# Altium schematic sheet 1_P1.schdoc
size 429 x 307 mm; Symbol: Drawing-Symbol_A4; Device: Drawing-Symbol_A4; Company: 嘉立创EDA; Version: V1.0; Page Size: A4; @Project Name: 数控直流电源v3; @Page Count: 1; @Update Date: 2025-11-23; @Create Date: 2025-11-23; @Schematic Name: v3; @Page No: 1; @Page Name: P1; @Create Time: 16:35:47; @Update Time: 18:46:06; Width: 1655; Height: 1170; Region Start: 1; X Region Count: 6; Y Region Count: 4; Blade Width: 10; Title Block Position: 3; @Board Name: Board1
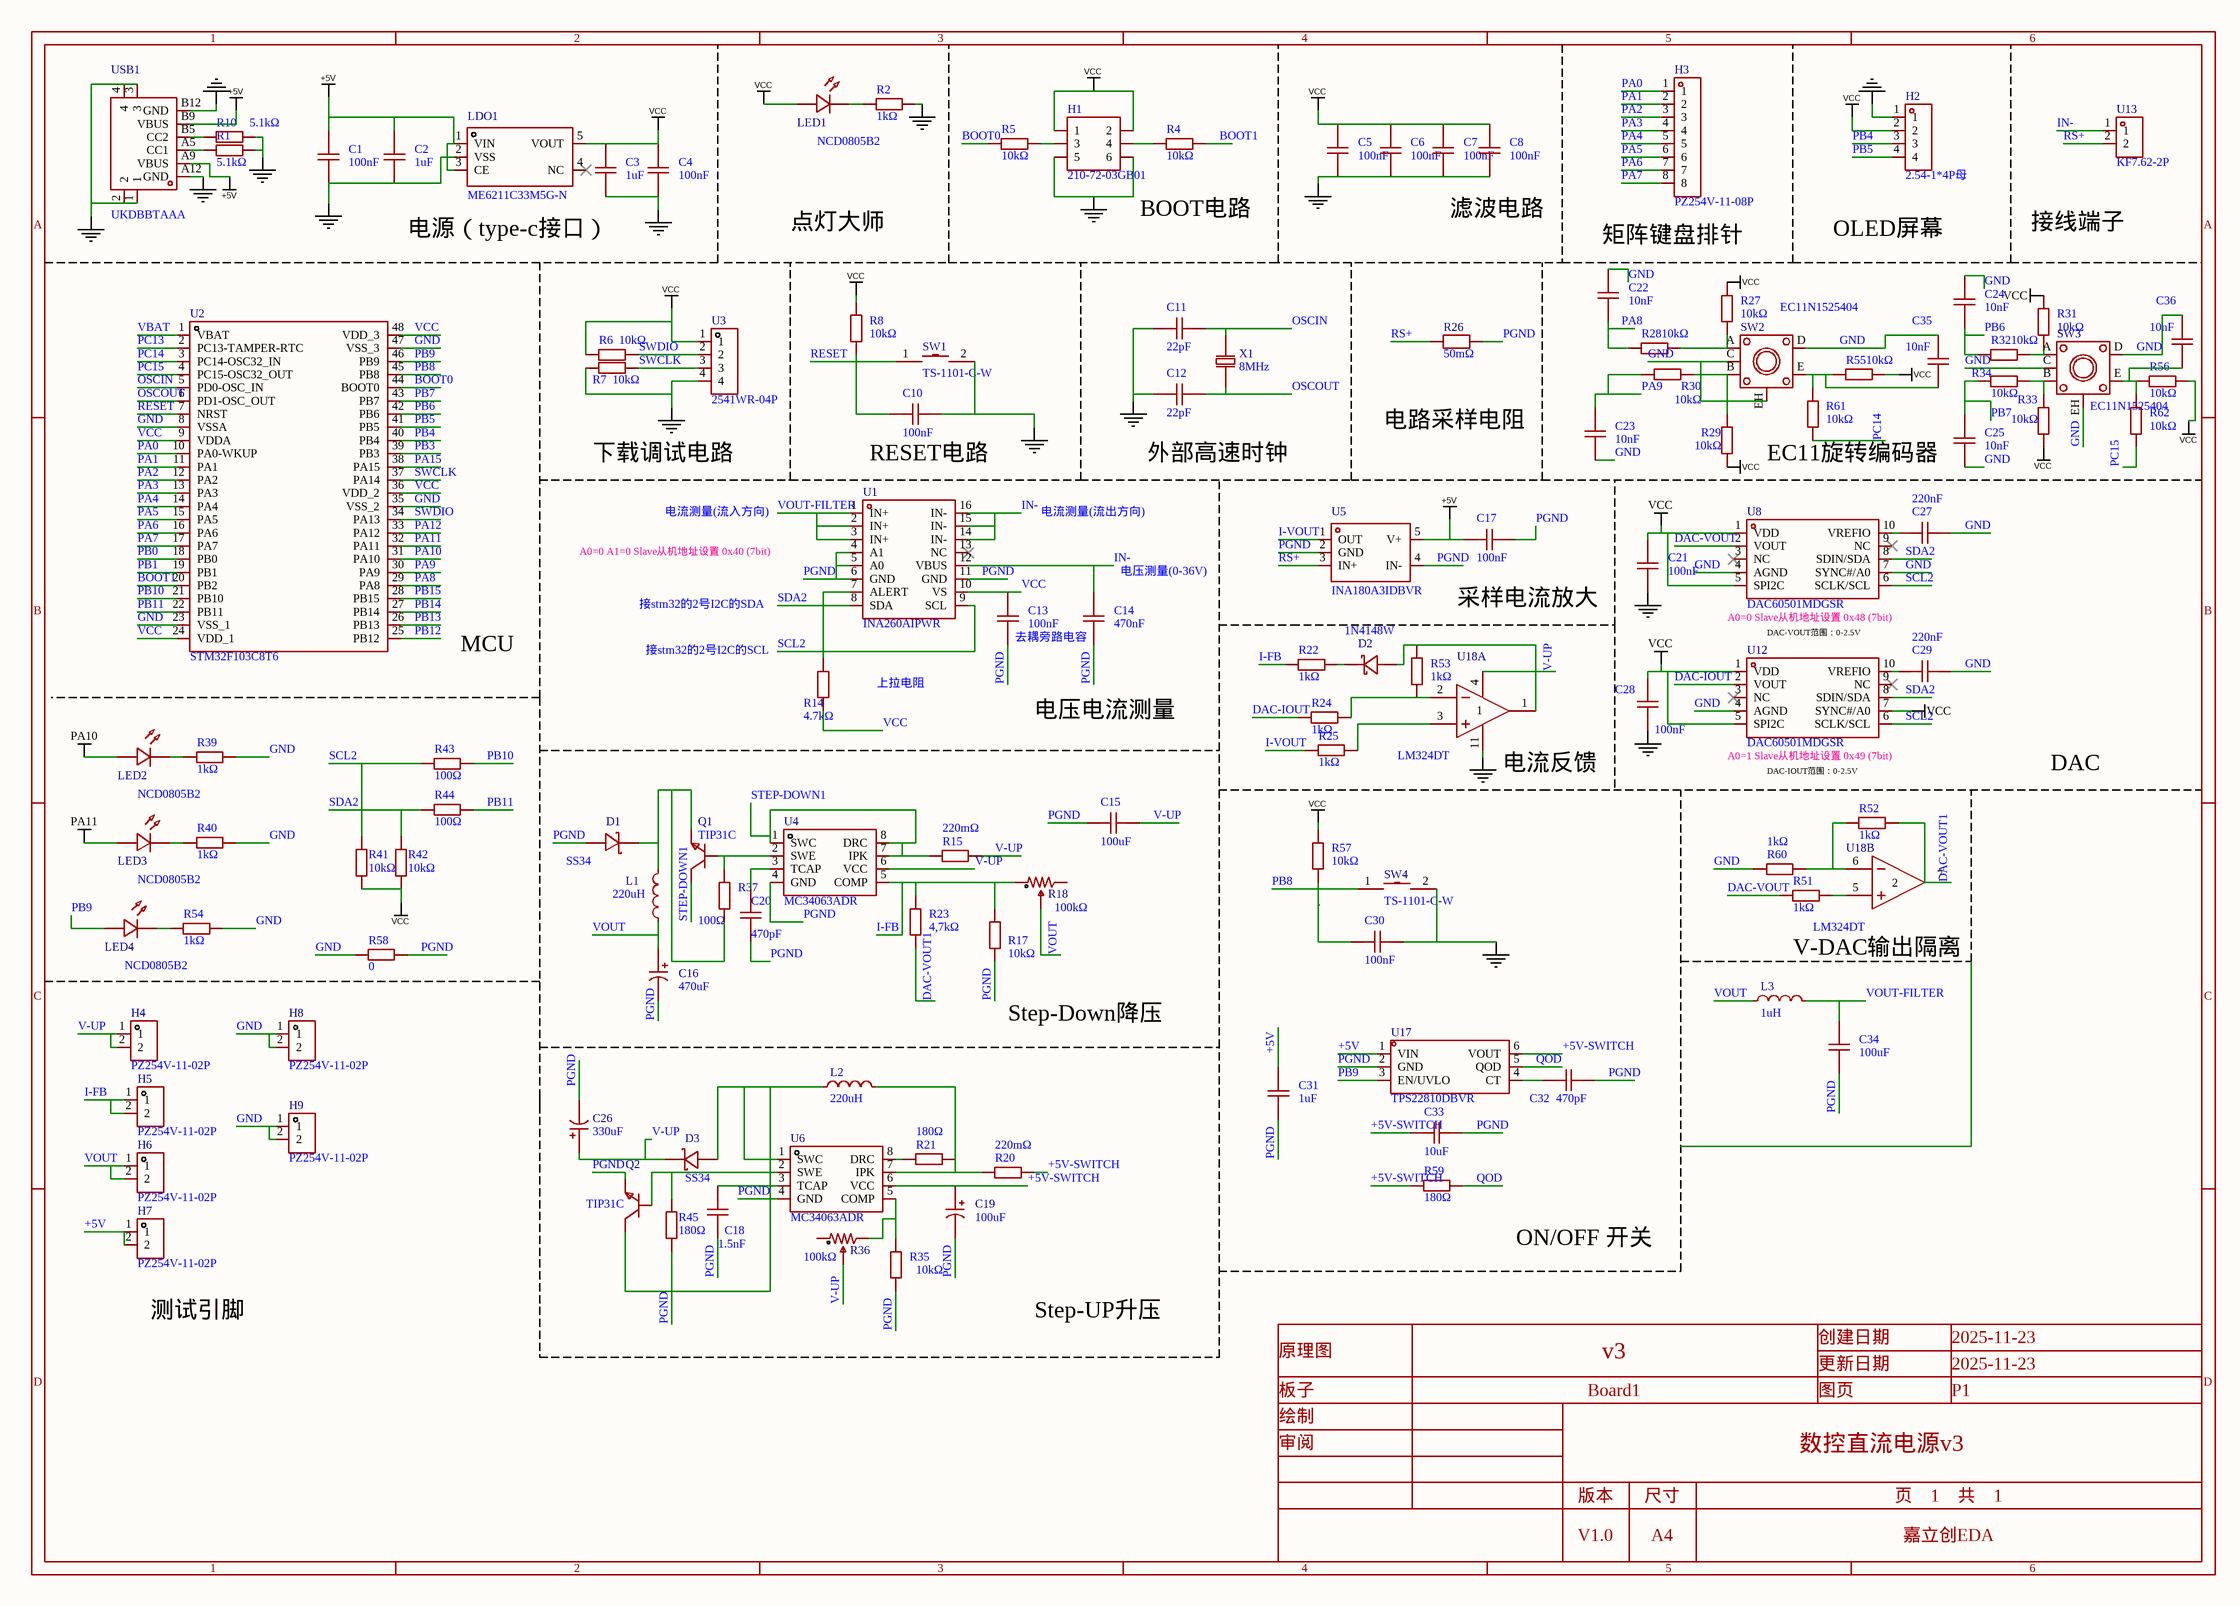
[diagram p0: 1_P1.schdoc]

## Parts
C1  100nF  [C0805]
C2  1uF  [C0805]
C3  1uF  [C0805]
C4  100nF  [C0805]
C5  100nF  [C0805]
C6  100nF  [C0805]
C7  100nF  [C0805]
C8  100nF  [C0805]
C10  100nF  [C0805]
C11  22pF  [C0805]
C12  22pF  [C0805]
C13  100nF  [C0805]
C14  470nF  [C0805]
C15  100uF  [CAP-SMD_BD6.3-L6.6-W6.6-RD]
C16  470uF  [CAP-SMD_BD8.0-L8.3-W8.3-LS9.0-FD_H10.5]
C17  100nF  [C0805]
C18  1.5nF  [C0805]
C19  100uF  [CAP-SMD_BD6.3-L6.6-W6.6-RD]
C20  470pF  [C0805]
C21  100nF  [C0805]
C22  10nF  [C0805]
C23  10nF  [C0805]
C24  10nF  [C0805]
C25  10nF  [C0805]
C26  330uF  [CAP-SMD_BD10.0-L10.3-W10.3-FD-LS11.0_H12.0]
C27  220nF  [C0805]
C28  100nF  [C0805]
C29  220nF  [C0805]
C30  100nF  [C0805]
C31  1uF  [C0805]
C32  470pF  [C0805]
C33  10uF  [C0805]
C34  100uF  [CAP-SMD_BD6.3-L6.6-W6.6-RD]
C35  10nF  [C0805]
C36  10nF  [C0805]
D1  SS34  [SMA_L4.3-W2.6-LS5.0-FD]
D2  1N4148W  [SOD-123_L2.7-W1.6-LS3.7-FD]
D3  SS34  [SMA_L4.3-W2.6-LS5.0-FD]
H1  210-72-03GB01  [HDR-TH_6P-P2.54-V-R2-C3-S2.54_A2541WV-2X3P]
H2  2.54-1*4P母  [HDR-TH_4P-P2.54-V-F]
H3  PZ254V-11-08P  [HDR-TH_8P-P2.54-V-M]
H4  PZ254V-11-02P  [HDR-TH_2P-P2.54-V-M]
H5  PZ254V-11-02P  [HDR-TH_2P-P2.54-V-M]
H6  PZ254V-11-02P  [HDR-TH_2P-P2.54-V-M]
H7  PZ254V-11-02P  [HDR-TH_2P-P2.54-V-M]
H8  PZ254V-11-02P  [HDR-TH_2P-P2.54-V-M]
H9  PZ254V-11-02P  [HDR-TH_2P-P2.54-V-M]
L1  220uH  [IND-SMD_L12.3-W12.3_SMDRI127]
L2  220uH  [IND-SMD_L12.3-W12.3_SMDRI127]
L3  1uH  [IND-SMD_L7.0-W6.6]
LDO1  ME6211C33M5G-N  [SOT-23-5_L3.0-W1.7-P0.95-LS2.8-BL]
LED1  NCD0805B2  [LED0805-R-RD]
LED2  NCD0805B2  [LED0805-R-RD]
LED3  NCD0805B2  [LED0805-R-RD]
LED4  NCD0805B2  [LED0805-R-RD]
Q1  TIP31C  [TO-220-3_L10.0-W4.5-P2.54-L]
Q2  TIP31C  [TO-220-3_L10.0-W4.5-P2.54-L]
R1  5.1kΩ  [R0805]
R2  1kΩ  [R0805]
R4  10kΩ  [R0805]
R5  10kΩ  [R0805]
R6  10kΩ  [R0805]
R7  10kΩ  [R0805]
R8  10kΩ  [R0805]
R10  5.1kΩ  [R0805]
R14  4.7kΩ  [R0805]
R15  220mΩ  [R1206]
R17  10kΩ  [R0805]
R18  100kΩ  [RES-ADJ-TH_3296W]
R20  220mΩ  [R1206]
R21  180Ω  [R0805]
R22  1kΩ  [R0805]
R23  4,7kΩ  [R0805]
R24  1kΩ  [R0805]
R25  1kΩ  [R0805]
R26  50mΩ  [R1206]
R27  10kΩ  [R0805]
R28  10kΩ  [R0805]
R29  10kΩ  [R0805]
R30  10kΩ  [R0805]
R31  10kΩ  [R0805]
R32  10kΩ  [R0805]
R33  10kΩ  [R0805]
R34  10kΩ  [R0805]
R35  10kΩ  [R0805]
R36  100kΩ  [RES-ADJ-TH_3296W-1-203]
R37  100Ω  [R0805]
R39  1kΩ  [R0805]
R40  1kΩ  [R0805]
R41  10kΩ  [R0805]
R42  10kΩ  [R0805]
R43  100Ω  [R0805]
R44  100Ω  [R0805]
R45  180Ω  [R0805]
R51  1kΩ  [R0805]
R52  1kΩ  [R0805]
R53  1kΩ  [R0805]
R54  1kΩ  [R0805]
R55  10kΩ  [R0805]
R56  10kΩ  [R0805]
R57  10kΩ  [R0805]
R58  0  [R0805]
R59  180Ω  [R0805]
R60  1kΩ  [R0805]
R61  10kΩ  [R0805]
R62  10kΩ  [R0805]
SW1  TS-1101-C-W  [SW-SMD_L6.0-W3.3-LS8.0]
SW2  EC11N1525404  [SW-TH_EC11NXXXX]
SW3  EC11N1525404  [SW-TH_EC11NXXXX]
SW4  TS-1101-C-W  [SW-SMD_L6.0-W3.3-LS8.0]
U1  INA260AIPWR  [TSSOP-16_L5.0-W4.4-P0.65-LS6.4-BL-1]
U2  STM32F103C8T6  [LQFP-48_L7.0-W7.0-P0.50-LS9.0-BL]
U3  2541WR-04P  [HDR-TH_4P-P2.54-H-M-W10.4-N]
U4  MC34063ADR  [SOIC-8_L4.9-W3.9-P1.27-LS6.0-BL]
U5  INA180A3IDBVR  [SOT-23-5_L3.0-W1.7-P0.95-LS2.8-BR]
U6  MC34063ADR  [SOIC-8_L4.9-W3.9-P1.27-LS6.0-BL]
U8  DAC60501MDGSR  [VSSOP-10_L3.0-W3.0-P0.50-LS4.9-BL]
U12  DAC60501MDGSR  [VSSOP-10_L3.0-W3.0-P0.50-LS4.9-BL]
U13  KF7.62-2P  [CONN-TH_KF7.62-2P]
U17  TPS22810DBVR  [SOT-23-6_L2.9-W1.6-P0.95-LS2.8-BL]
U18  LM324DT  [SOIC-14_L8.7-W3.9-P1.27-LS6.0-BL]  (parts A,B of 4)
USB1  UKDBBTAAA  [USB-C-SMD]
X1  8MHz  [CRYSTAL-TH_L11.1-W4.7-P4.88]

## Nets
+5V: C1.2 C2.2 C17.1 C31.2 H7.1 H7.2 LDO1.1(VIN) LDO1.3(CE) U5.5(V+) U17.1(VIN) USB1.A9(VBUS) USB1.B9(VBUS)
GND: C1.1 C2.1 C3.1 C4.1 C5.1 C6.1 C7.1 C8.1 C10.2 C11.1 C12.1 C21.1 C22.2 C23.1 C24.2 C25.1 C27.1 C28.1 C29.1 C30.2 C35.2 C36.2 H1.5 H1.6 H2.1 H8.1 H8.2 H9.1 H9.2 LDO1.2(VSS) R1.2 R2.2 R7.1 R10.2 R39.2 R40.2 R54.2 R58.1 R60.1 SW1.2 SW2.C SW2.D SW2.EH SW3.C SW3.D SW3.EH SW4.2 U2.8(VSSA) U2.23(VSS_1) U2.35(VSS_2) U2.47(VSS_3) U3.4 U8.4(AGND) U8.7(SYNC#/A0) U12.4(AGND) U18.11(VCC-) USB1.1 USB1.2 USB1.3 USB1.4 USB1.A12(GND) USB1.B12(GND)
PA10: LED2.2(A) U2.31(PA10)
PA11: LED3.2(A) U2.32(PA11)
VCC: C3.2 C4.2 C5.2 C6.2 C7.2 C8.2 C13.2 C21.2 C28.2 H1.1 H1.2 H2.2 LDO1.5(VOUT) LED1.2(A) R6.1 R8.2 R14.1 R27.2 R29.1 R31.2 R33.1 R41.1 R42.1 R55.2 R56.1 R57.2 U1.10(VS) U2.9(VDDA) U2.24(VDD_1) U2.36(VDD_2) U2.48(VDD_3) U3.1 U8.1(VDD) U8.5(SPI2C) U12.1(VDD) U12.5(SPI2C) U12.7(SYNC#/A0)
+5V-SWITCH: C19.1 C33.1 R20.2 R59.1 U6.6(VCC) U17.6(VOUT)
BOOT0: R5.1 U2.44(BOOT0)
BOOT1: R4.2 U2.20(PB2)
DAC-IOUT: R24.1 U12.2(VOUT)
DAC-VOUT: R51.1 U8.2(VOUT)
DAC-VOUT1: R23.1 R52.2 U18.7(OUT2)
I-FB: H5.1 H5.2 R17.2 R18.1 R22.1 R23.2 U4.5(COMP)
I-VOUT: R25.1 U5.1(OUT)
IN-: C14.2 U1.12(VBUS) U1.14(IN-) U1.15(IN-) U1.16(IN-) U13.1
OSCIN: C11.2 U2.5(PD0-OSC_IN) X1.2
OSCOUT: C12.2 U2.6(PD1-OSC_OUT) X1.1
PA0: H3.1 U2.10(PA0-WKUP)
PA1: H3.2 U2.11(PA1)
PA2: H3.3 U2.12(PA2)
PA3: H3.4 U2.13(PA3)
PA4: H3.5 U2.14(PA4)
PA5: H3.6 U2.15(PA5)
PA6: H3.7 U2.16(PA6)
PA7: H3.8 U2.17(PA7)
PA8: C22.1 R28.1 U2.29(PA8)
PA9: C23.2 R30.1 U2.30(PA9)
PA12: U2.33(PA12)
PA15: U2.38(PA15)
PB0: U2.18(PB0)
PB1: U2.19(PB1)
PB3: U2.39(PB3)
PB4: H2.3 U2.40(PB4)
PB5: H2.4 U2.41(PB5)
PB6: C24.1 R32.1 U2.42(PB6)
PB7: C25.2 R34.1 U2.43(PB7)
PB8: C30.1 R57.1 SW4.1 U2.45(PB8)
PB9: LED4.2(A) U2.46(PB9) U17.3(EN/UVLO)
PB10: R43.2 U2.21(PB10)
PB11: R44.2 U2.22(PB11)
PB12: U2.25(PB12)
PB13: U2.26(PB13)
PB14: U2.27(PB14)
PB15: U2.28(PB15)
PC13: U2.2(PC13-TAMPER-RTC)
PC14: R61.1 U2.3(PC14-OSC32_IN)
PC15: R62.1 U2.4(PC15-OSC32_OUT)
PGND: C13.1 C14.1 C15.2 C16.2 C17.2 C18.1 C19.2 C20.1 C26.2 C31.1 C32.2 C33.2 C34.2 D1.2(A) Q2.3(E) R17.1 R26.2 R35.1 R45.2 R58.2 U1.4(A1) U1.5(A0) U1.6(GND) U1.11(GND) U4.4(GND) U5.2(GND) U5.4(IN-) U6.4(GND) U17.2(GND)
QOD: R59.2 U17.5(QOD)
RESET: C10.1 R8.1 SW1.1 U2.7(NRST)
RS+: R26.1 U5.3(IN+) U13.2
SCL2: R41.2 R43.1 U1.9(SCL) U8.6(SCLK/SCL) U12.6(SCLK/SCL)
SDA2: R42.2 R44.1 U1.8(SDA) U8.8(SDIN/SDA) U12.8(SDIN/SDA)
STEP-DOWN1: Q1.2(C) R15.2 U4.1(SWC) U4.7(IPK) U4.8(DRC)
SWCLK: R7.2 U2.37(PA14) U3.3
SWDIO: R6.2 U2.34(PA13) U3.2
V-UP: C15.1 C26.1 D3.1(K) H4.1 H4.2 R15.1 R36.2 U4.6(VCC) U18.4(VCC+)
VBAT: U2.1(VBAT)
VOUT: C16.1 H6.1 H6.2 L1.1 L3.1 R18.2
VOUT-FILTER: C34.1 L3.2 U1.1(IN+) U1.2(IN+) U1.3(IN+)
NetC18_2: C18.2 U6.3(TCAP)
NetC20_2: C20.2 U4.3(TCAP)
NetC27_2: C27.2 U8.10(VREFIO)
NetC29_2: C29.2 U12.10(VREFIO)
NetC32_1: C32.1 U17.4(CT)
NetC35_1: C35.1 R55.1 R61.2 SW2.E
NetC36_1: C36.1 R56.2 R62.2 SW3.E
NetD1_1: D1.1(K) L1.2 Q1.3(E) R37.1
NetD2_1: D2.1(A) R53.2 U18.1(OUT1)
NetD2_2: D2.2(K) R22.2
NetD3_2: D3.2(A) L2.1 Q2.2(C) U6.1(SWC)
NetH1_3: H1.3 R5.2
NetH1_4: H1.4 R4.1
NetL2_2: L2.2 R20.1 R21.2 U6.7(IPK)
NetLED1_1: LED1.1(C) R2.1
NetLED2_1: LED2.1(C) R39.1
NetLED3_1: LED3.1(C) R40.1
NetLED4_1: LED4.1(C) R54.1
NetQ1_1: Q1.1(B) R37.2 U4.2(SWE)
NetQ2_1: Q2.1(B) R45.1 U6.2(SWE)
NetR1_1: R1.1 USB1.A5(CC1)
NetR10_1: R10.1 USB1.B5(CC2)
NetR14_2: R14.2 U1.7(ALERT)
NetR21_1: R21.1 U6.8(DRC)
NetR24_2: R24.2 R53.1 U18.2(IN1-)
NetR25_2: R25.2 U18.3(IN1+)
NetR27_1: R27.1 R28.2 SW2.A
NetR29_2: R29.2 R30.2 SW2.B
NetR31_1: R31.1 R32.2 SW3.A
NetR33_2: R33.2 R34.2 SW3.B
NetR35_2: R35.2 R36.3 U6.5(COMP)
NetR51_2: R51.2 U18.5(IN2+)
NetR52_1: R52.1 R60.2 U18.6(IN2-)

Not connected (* = marked no-connect by the designer): LDO1 4(NC)*; R18 3; R36 1; U1 13(NC)*; U8 3(NC)* 9(NC)*; U12 3(NC)* 9(NC)*

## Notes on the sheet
- 电源（type-c接口）
- 点灯大师
- BOOT电路
- 滤波电路
- OLED屏幕
- 接线端子
- 矩阵键盘排针
- 电路采样电阻
- 下载调试电路
- (near C10) RESET电路
- 外部高速时钟
- (near R61) EC11旋转编码器
- A0=0 A1=0 Slave从机地址设置 0x40 (7bit)
- 电流测量(流入方向)
- 电流测量(流出方向)
- (near C14) 电压测量(0-36V)
- 接stm32的2号I2C的SDA
- 采样电流放大
- (near U8) A0=0 Slave从机地址设置 0x48 (7bit)
- DAC-VOUT范围：0-2.5V
- MCU
- 接stm32的2号I2C的SCL
- 上拉电阻
- (near C13) 去耦旁路电容
- 电压电流测量
- (near U12) A0=1 Slave从机地址设置 0x49 (7bit)
- (near U18) 电流反馈
- DAC-IOUT范围：0-2.5V
- DAC
- V-DAC输出隔离
- Step-Down降压
- ON/OFF 开关
- 测试引脚
- Step-UP升压

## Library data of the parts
C1 C4-C8 C10 C13 C17 C21 C28 C30 = 0805B104K500NT: Manufacturer: FH(风华); Symbol: Capacitance; Add into BOM: yes; Tolerance: ±10%; Voltage Rating: 50V; Temperature Coefficient: X7R
C2 C3 C31 = CL21B105KBFNNNE: Manufacturer: SAMSUNG(三星); Symbol: Capacitance; Add into BOM: yes; Tolerance: ±10%; Voltage Rating: 50V; Temperature Coefficient: X7R
C11 C12 = 0805CG220J500NT: Manufacturer: FH(风华); Symbol: Capacitance; Add into BOM: yes; Tolerance: ±5%; Voltage Rating: 50V; Temperature Coefficient: C0G
C14 = 0805B474K500NT: Manufacturer: FH(风华); Symbol: Capacitance; Add into BOM: yes; Tolerance: ±10%; Voltage Rating: 50V; Temperature Coefficient: X7R
C15 C34 = MA35V100M6X8: Manufacturer: JIERR(捷而瑞); Symbol: Capacitance; Add into BOM: yes; Tolerance: ±20%; Voltage Rating: 35V; Ripple Current: 2.9A@100kHz; Equivalent Series Resistance(ESR): 30mΩ@100kHz; Type: 聚合物; Lifetime: 2000hrs@105℃
C16 = MA25V470M8x10: Manufacturer: JIERR(捷而瑞); Symbol: JVJ25V470M8X10; Add into BOM: yes; Tolerance: ±20%; Voltage Rating: 25V; Ripple Current: 4.1A@100kHz; Equivalent Series Resistance(ESR): 25mΩ@100kHz; Type: 聚合物; Lifetime: 2000hrs@105℃
C18 = 0805B152K500NT: Manufacturer: FH(风华); Symbol: Capacitance; Add into BOM: yes; Tolerance: ±10%; Voltage Rating: 50V; Temperature Coefficient: X7R
C19 = MA35V100M6X8: Manufacturer: JIERR(捷而瑞); Symbol: JVJ25V100M6X5; Add into BOM: yes; Tolerance: ±20%; Voltage Rating: 35V; Ripple Current: 2.9A@100kHz; Equivalent Series Resistance(ESR): 30mΩ@100kHz; Type: 聚合物; Lifetime: 2000hrs@105℃
C20 C32 = 0805B471K500NT: Manufacturer: FH(风华); Symbol: Capacitance; Add into BOM: yes; Tolerance: ±10%; Voltage Rating: 50V; Temperature Coefficient: X7R
C22-C25 C35 C36 = 0805B103K500NT_C52278: Manufacturer: FH(风华); Symbol: Capacitance; Add into BOM: yes; Tolerance: ±10%; Voltage Rated: 50V; Temperature Coefficient: X7R
C26 = MA35V330M10x10: Manufacturer: JIERR(捷而瑞); Symbol: JVJ25V470M8X10; Add into BOM: yes; Tolerance: ±20%; Voltage Rating: 35V; Ripple Current: 3.5A@100kHz; Equivalent Series Resistance(ESR): 25mΩ@100kHz; Type: 聚合物; Lifetime: 2000hrs@105℃
C27 C29 = 0805B224K500NT: Manufacturer: FH(风华); Symbol: Capacitance; Add into BOM: yes; Tolerance: ±10%; Voltage Rating: 50V; Temperature Coefficient: X7R
C33 = CL21A106KAYNNNE_C15850: Manufacturer: SAMSUNG(三星); Symbol: Capacitance; Add into BOM: yes; Tolerance: ±10%; Voltage Rating: 25V; Temperature Coefficient: X5R
D1 D3 = SS34_C7420365: Manufacturer: R+O(宏嘉诚); Symbol: 1N5819WS; Add into BOM: yes; Diode Configuration: 独立式; Voltage - Forward(Vf@If): 550mV@3.0A; Voltage - DC Reverse(Vr): 40V; Current - Rectified: 3A; Reverse Leakage Current (Ir): 200uA@40V
D2 = 1N4148W_C7420318: Manufacturer: R+O(宏嘉诚); Add into BOM: yes; Diode Configuration: 独立式; Voltage - Forward(Vf@If): 1.25V@150mA; Voltage - DC Reverse(Vr): 100V; Current - Rectified: 150mA; Pd - Power Dissipation: 400mW; Reverse Leakage Current (Ir): 1uA@75V; Reverse Recovery Time (trr): 4ns; Operating Junction Temperature Range: -55℃~+150℃; Non-Repetitive Peak Forward Surge Current: 2A
H1 = 210-72-03GB01: Manufacturer: PINREX(频锐科技); Symbol: HDR-M-2.54_2x3; Add into BOM: yes; Pin Structure: 2x3P; Pitch: 2.54mm; Circluar Pins/Square Pins: 方针
H2 = 2.54-1*4P母: Manufacturer: BOOMELE(博穆精密); Add into BOM: yes; Holes Structure: 1x4P; Pitch: 2.54mm; Circular Hole / Square Hole: 方孔; Number of Positions: 4P; Current Rating: 3A; Holes Direction: 顶部
H3 = PZ254V-11-08P: Manufacturer: XFCN(兴飞); Add into BOM: yes; Pin Structure: 1x8P; Pitch: 2.54mm; Circluar Pins/Square Pins: 方针
H4-H9 = PZ254V-11-02P: Manufacturer: XFCN(兴飞); Add into BOM: yes; Pin Structure: 1x2P; Pitch: 2.54mm; Circluar Pins/Square Pins: 方针
L1 L2 = SMDRI127-221MT: Manufacturer: SXN(顺翔诺); Symbol: FNR5040S221MT; Add into BOM: yes; Tolerance: ±20%; Rated Current: 1.16A; Saturation Current (Isat): 2A; DC Resistance (DCR): 390mΩ; Type: 屏蔽电感
L3 = FXL0630-1R0-M: Manufacturer: cjiang(长江微电); Symbol: FXL0420-1R0-M; Add into BOM: yes; Tolerance: ±20%; Current Rating: 12A; Current - Saturation(Isat): 15A; DC Resistance(DCR): 7.4mΩ; Type: 一体成型电感
LDO1 = ME6211C33M5G-N: Manufacturer: MICRONE(南京微盟); Add into BOM: yes; Output Type: 固定; Voltage - Supply: 6V; Output Voltage: 3.3V; Output Current: 500mA; Power Supply Rejection Ratio (PSRR): 70dB@(1kHz); Voltage Dropout: 120mV@(100mA); standby current: 60uA; Noise: 50uVrms; Output Configuration: 正极; Number of Outputs: 1
LED1-LED4 = NCD0805B2: Manufacturer: 国星光电; Symbol: LED_R; Convert to PCB: yes; Emitted Color: 蓝色; Forward Voltage (VF): 2.5V~3.6V; Power Dissipation: 72mW; Forward Current: 2mA; Dominant Wavelength: 468nm~478nm; Lens Color: 无色透明透镜; Luminous Intensity: 20mcd~55mcd; Viewing Angle: 130°
Q1 Q2 = TIP31C_C963401: Manufacturer: JSMSEMI(杰盛微); Add into BOM: yes; type: NPN; Current - Collector(Ic): 3A; Collector - Emitter Voltage VCEO: 100V; Pd - Power Dissipation: 40W; DC Current Gain: 50@3A,4V; Transition frequency(fT): 3MHz; Current - Collector Cutoff: 200uA; Vce Saturation(VCE(sat)): 1.2V; Emitter-Base Voltage(Vebo): 5V
R1 R10 = 0805W8F5101T5E: Manufacturer: UNI-ROYAL(厚声); Symbol: 电阻; Add into BOM: yes; Tolerance: ±1%; Power(Watts): 125mW; Voltage-Supply(Max): 150V; Temperature Coefficient: ±100ppm/℃
R2 R22 R24 R25 R39 R40 R51-R54 R60 = 0805W8F1001T5E: Manufacturer: UNI-ROYAL(厚声); Symbol: 电阻; Add into BOM: yes; Tolerance: ±1%; Power(Watts): 125mW; Overload Voltage (Max): 150V; Temperature Coefficient: ±100ppm/℃
R4-R8 R17 R23 R27-R35 R41 R42 R55-R57 R61 R62 = 0805W8F1002T5E_C17414: Manufacturer: UNI-ROYAL(厚声); Symbol: 电阻; Add into BOM: yes; Tolerance: ±1%; Power(Watts): 125mW; Voltage-Supply(Max): 150V; Temperature Coefficient: ±100ppm/℃
R14 = 0805W8F4701T5E: Manufacturer: UNI-ROYAL(厚声); Symbol: 电阻; Add into BOM: yes; Tolerance: ±1%; Power(Watts): 125mW; Overload Voltage (Max): 150V; Temperature Coefficient: ±100ppm/℃
R15 R20 = FRL1206FR220TS: Manufacturer: FOJAN(富捷); Symbol: 电阻; Add into BOM: yes; Tolerance: ±1%; Power(Watts): 250mW; Voltage-Supply(Max): 500V; Temperature Coefficient: ±300ppm/℃
R18 = 3296W-1-104LF: Manufacturer: BOURNS; Symbol: 3296W-1-103_C48997937; Add into BOM: yes; Tolerance: ±10%; Power(Watts): 500mW; Temperature Coefficient: ±100ppm/℃; Number of Turns: 25
R21 R45 R59 = 0805W8F1800T5E: Manufacturer: UNI-ROYAL(厚声); Symbol: 电阻; Add into BOM: yes; Tolerance: ±1%; Power(Watts): 125mW; Voltage-Supply(Max): 150V; Temperature Coefficient: ±100ppm/℃
R26 = RE1206F1R050: Manufacturer: JIERR(捷而瑞); Add into BOM: yes; Tolerance: ±1%; Power(Watts): 1W; Temperature Coefficient: ±50ppm/℃
R36 = 3296W-1-104_C48997936: Manufacturer: JIERR(捷而瑞); Symbol: 3296W-1-103_C48997937; Add into BOM: yes; Tolerance: ±10%; Power(Watts): 500mW; Temperature Coefficient: ±250ppm/℃; Number of Turns: 28
R37 R43 R44 = 0805W8F1000T5E: Manufacturer: UNI-ROYAL(厚声); Symbol: 电阻; Add into BOM: yes; Tolerance: ±1%; Power(Watts): 125mW; Overload Voltage (Max): 150V; Temperature Coefficient: ±100ppm/℃
R58 = Res_0805: Symbol: 电阻; Convert to PCB: yes
SW1 SW4 = TS-1101-C-W: Manufacturer: XKB Connectivity(中国星坤); Add into BOM: yes; Circuit: 单刀单掷; Actuator Style: 矩形按钮; Operating Force: 260gf; Switch Length: 6mm; Switch Width: 3.6mm; Switch Height: 2.5mm; Strike Gundam: 不带; Contact Current: 50mA; Voltage Rating (DC): 12V; Actuator/Cap Color: 白色带淡绿; With Lamp: 无; Mechanical Life: 5万次
SW2 SW3 = EC11N1525404: Manufacturer: ALPSALPINE(阿尔卑斯阿尔派); Add into BOM: yes
U1 = INA260AIPWR: Manufacturer: TI(德州仪器); Add into BOM: yes
U2 = STM32F103C8T6: Manufacturer: ST(意法半导体); Add into BOM: yes; CPU Core: ARM-M3; CPU Maximum Speed: 72MHz; Program Storage Size: 64KB; Program Memory Type: FLASH; Number of I/O: 37; ADC (Bit): 12bit; Voltage - Supply: 2V~3.6V
U3 = 2541WR-04P: Manufacturer: HanElectricity(瀚源); Add into BOM: yes; Pin Structure: 1x4P; Pitch: 2.54mm; Circluar Pins/Square Pins: 方针
U4 U6 = MC34063ADR: Manufacturer: TI(德州仪器); Add into BOM: yes; Function: 升压型；降压型; Voltage - Supply: 3V~40V; Output Current: 1.5A; Frequency - Switching: 100kHz; Synchronous Rectifier: 否; Number of Outputs: 1; Topology: 降压式；升压式；反相式; Switch tube (built-in/external): 内置; Output Type: 可调
U5 = INA180A3IDBVR: Manufacturer: TI(德州仪器); Add into BOM: yes; Number of Channels: 单路; Vcm - Common Mode Voltage: -200mV~26V; Gain: 100V/V; Bandwidth: 150kHz; Voltage - Supply: 2.7V~5.5V
U8 U12 = DAC60501MDGSR: Manufacturer: TI(德州仪器); Add into BOM: yes; Resolution(Bits): 12位; Number of Channels: 1; Interface: SPI；I2C; Voltage - Supply: 2.7V~5.5V; Settling Time: 5us; Output Type: 电压-缓冲; Integral non - linearity: 1LSB; Power-On Reset: 内置; Voltage Reference Drift: 5ppm/℃; Data rate: 1MHz；50MHz；100kHz；400kHz; Supply Current (Iq): 15uA
U13 = KF7.62-2P: Manufacturer: KEFA(科发); Add into BOM: yes; Barrier Type: 两面; Pitch: 7.62mm; Structure: 1x2P; Pin Location: 边脚; Current Rating (Max): 24A; Voltage Rating (Max): 450V; Wire Gauge - AWG: 12~22; Wire Gauge - mm2: 2.5; Number of PINs Per Row: 2
U17 = TPS22810DBVR: Manufacturer: TI(德州仪器); Add into BOM: yes; Number of Channels: 1; Control Input Logic: 高电平有效; Maximum Continuous Current: 2A; Voltage - Supply: 2.7V~18V; RDS(on): 79mΩ
U18 = LM324DT: Manufacturer: ST(意法半导体); Add into BOM: yes; Number of Channels: 四路; Maximum Power Supply Range (Vdd-Vss): 30V; Gain Bandwidth Product: 1.3MHz; Vos - Input Offset Voltage: 5mV; Input Offset Voltage Drift(Vos TC): 30uV/℃; Slew Rate: 20V/us; Ib - Input Bias Current: 300nA; Input Offset Current(Ios): 20nA; Noise density(eN): 40nV/√Hz@1kHz; Common Mode Rejection Ratio(CMRR): 80dB; Input offset current drift(Ios TC): 200pA/℃; Quiescent Current: 1.2mA; Output Current: 70mA; Single supply: 3V~30V; Dual Supply: -15V~-1.5V；1.5V~15V; Relevance: []
USB1 = UKDBBTAAA: Manufacturer: SAMZO(三佐); Add into BOM: yes; Connector Type: Type-C; Protocol Standard: USB 3.1; Gender: 母; Number of Contacts: 6P; Number of Ports: 1; Current Rating-Power: 3A; Voltage Rating: 5V; Connect-Disconnect Life: 3千次; Detection color: 黑色
X1 = YG8MLBBE2X: Manufacturer: YJX(雅晶鑫); Add into BOM: yes; Normal temperature Frequency Tolerance: ±10ppm; Load Capacitance: 20pF; Frequency Stability: ±30ppm; Equivalent Series Resistance(ESR): 80Ω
